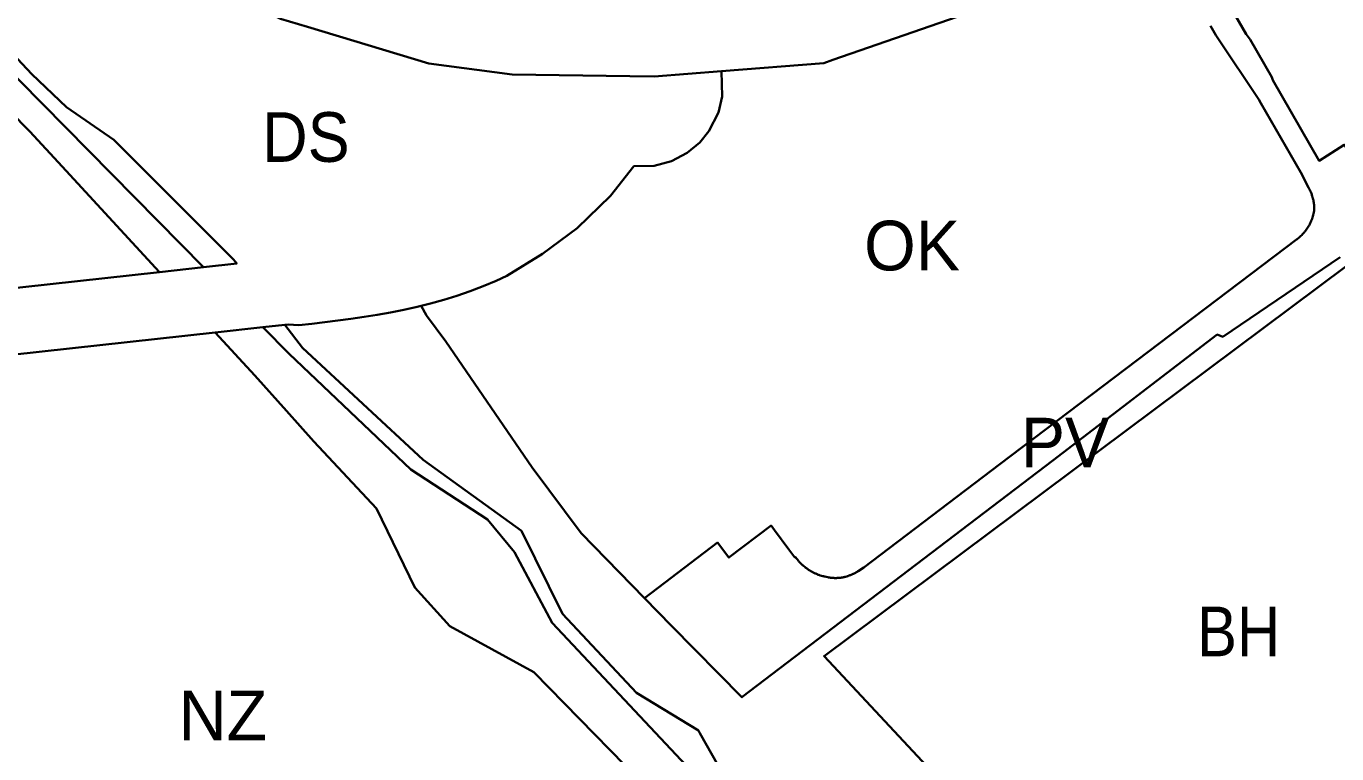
# Model space of a CAD drawing. Extents: x -650451 to -642268, y -1075216 to -1066610.
# Drawn here: x -646953.6 to -646557.7, y -1072322.1 to -1072102.4 of the extents above; entities that cross this region are included whole.
import ezdxf

# ---------------------------------------------------------------- set-up
doc = ezdxf.new("R2010")
doc.units = 0
doc.header["$LTSCALE"] = 6
doc.layers.add('1', color=7, linetype='Continuous', lineweight=35)
doc.layers.add('2', color=7, linetype='Continuous')
doc.layers.add('3', color=7, linetype='Continuous')

msp = doc.modelspace()

# ---------------------------------------------------------------- linework, layer by layer
at = {"layer": '1'}
for p, q in [((-646968.503, -1072182.672), (-646913.373, -1072176.618)), ((-646913.373, -1072176.618), (-646900.046, -1072175.154)), ((-646896.524, -1072194.888), (-646882.135, -1072193.308)), ((-646875.509, -1072192.58), (-646882.135, -1072193.308))]:
    msp.add_line(p, q, dxfattribs=at)
for points in [[(-647265.83, -1071793.64), (-647262.68, -1071796.7), (-647221.71, -1071838.15), (-647177.46, -1071886.9), (-647104.1, -1071962.84), (-647060.23, -1072007.95), (-647027.11, -1072042.92), (-646955.57, -1072118.88), (-646900.046, -1072175.154)], [(-646913.373, -1072176.618), (-646942.78, -1072144.74), (-646952.48, -1072134.22), (-646964.8, -1072121.83), (-646977.59, -1072108.96), (-646978.45, -1072108.09), (-647036.8, -1072048.41), (-647068.31, -1072015.68), (-647114.59, -1071967.77), (-647145.38, -1071935), (-647173.14, -1071905.45), (-647174.57, -1071904.06), (-647176.32, -1071902.3)], [(-646743.596, -1072115.986), (-646763.93, -1072117.61), (-646771.31, -1072117.49), (-646806.87, -1072116.94), (-646832.01, -1072113.66), (-646868.61, -1072102.6), (-646876.83, -1072100.12), (-646956.04, -1072061.95), (-646996.8, -1072034.35), (-647040.89, -1071996.58), (-647067.53, -1071967.54), (-647095.51, -1071938.39), (-647114.479, -1071912.479)], [(-646900.046, -1072175.154), (-646890.044, -1072174.056), (-646891.05, -1072172.79), (-646927.14, -1072136.74), (-646941.45, -1072126.84), (-646951.95, -1072116.84), (-646966.54, -1072101.4), (-646967.25, -1072100.6), (-646981.35, -1072085.77), (-647023.04, -1072041.63), (-647055.16, -1072007.74), (-647101.07, -1071960.24), (-647131.146, -1071929.146)], [(-646548.676, -1072166.737), (-646539.94, -1072160.83), (-646555.49, -1072138.17), (-646563.11, -1072143.03), (-646577.08, -1072118.7), (-646577.41, -1072117.76), (-646583.9, -1072106.42), (-646585.08, -1072104.81), (-646591.02, -1072094.4), (-646593.13, -1072091.01), (-646595.86, -1072086.82), (-646598.67, -1072081.55), (-646600.22, -1072077.86), (-646600.8, -1072075.94), (-646601.16, -1072074.07), (-646601.42, -1072071.01), (-646601, -1072067.55)], [(-646619.27, -1072080.81), (-646621.63, -1072079.85), (-646625.15, -1072078.98), (-646625.414, -1072079.188), (-646634.85, -1072086.5), (-646709.94, -1072112.55), (-646712.72, -1072113.52), (-646743.596, -1072115.986)], [(-646569.541, -1072166.508), (-646569.256, -1072166.279), (-646568.977, -1072166.042), (-646568.703, -1072165.797), (-646568.613, -1072165.714), (-646568.348, -1072165.458), (-646568.09, -1072165.196), (-646567.922, -1072165.017), (-646567.757, -1072164.835), (-646567.676, -1072164.743), (-646567.516, -1072164.556), (-646567.36, -1072164.367), (-646567.207, -1072164.175), (-646566.984, -1072163.882), (-646566.77, -1072163.583), (-646566.564, -1072163.279), (-646566.367, -1072162.971), (-646566.179, -1072162.657), (-646566.118, -1072162.552), (-646566, -1072162.34), (-646565.906, -1072162.16), (-646565.771, -1072161.887), (-646565.684, -1072161.703), (-646565.559, -1072161.424), (-646565.441, -1072161.142), (-646565.365, -1072160.952), (-646565.293, -1072160.761), (-646565.223, -1072160.569), (-646565.093, -1072160.181), (-646564.975, -1072159.789), (-646564.895, -1072159.493), (-646564.845, -1072159.295), (-646564.799, -1072159.096), (-646564.755, -1072158.896), (-646564.696, -1072158.596), (-646564.661, -1072158.395), (-646564.628, -1072158.194), (-646564.599, -1072157.993), (-646564.573, -1072157.792), (-646564.55, -1072157.59), (-646564.559, -1072157.196), (-646564.58, -1072156.802), (-646564.589, -1072156.671), (-646564.625, -1072156.276), (-646564.656, -1072156.013), (-646564.673, -1072155.882), (-646564.712, -1072155.62), (-646564.755, -1072155.358), (-646564.83, -1072154.967), (-646564.887, -1072154.707), (-646564.948, -1072154.449), (-646564.981, -1072154.32), (-646565.05, -1072154.064), (-646565.125, -1072153.808), (-646565.164, -1072153.681), (-646565.245, -1072153.429), (-646565.332, -1072153.178), (-646565.423, -1072152.929), (-646565.519, -1072152.683), (-646565.62, -1072152.438), (-646565.672, -1072152.317), (-646565.78, -1072152.076), (-646565.892, -1072151.838), (-646565.95, -1072151.72), (-646566.069, -1072151.486), (-646566.264, -1072151.112), (-646568.62, -1072146.55), (-646580.67, -1072125.63), (-646581.29, -1072124.56), (-646593.681, -1072106.013), (-646594.232, -1072105.088), (-646595.86, -1072102.267)], [(-646834.294, -1072186.789), (-646831.517, -1072186.103), (-646827.501, -1072184.997), (-646823.496, -1072183.769), (-646819.509, -1072182.408), (-646815.549, -1072180.906), (-646811.621, -1072179.254), (-646808.466, -1072177.78), (-646797.713, -1072171.151), (-646787.223, -1072163.402), (-646777.129, -1072153.576), (-646770.057, -1072144.677), (-646763.959, -1072144.535), (-646758.736, -1072143.137), (-646753.929, -1072140.612), (-646750.164, -1072137.467), (-646747.39, -1072134.069), (-646744.554, -1072128.415), (-646743.411, -1072123.612), (-646743.596, -1072115.986)], [(-646766.842, -1072275.063), (-646744.78, -1072258.29), (-646741.34, -1072262.83), (-646728.61, -1072253.17), (-646727.59, -1072254.59), (-646723.26, -1072260.35), (-646721.42, -1072262.78), (-646721.28, -1072262.7), (-646720.37, -1072263.85), (-646720.236, -1072263.999), (-646719.961, -1072264.294), (-646719.82, -1072264.439), (-646719.677, -1072264.582), (-646719.531, -1072264.723), (-646719.384, -1072264.863), (-646719.235, -1072265.001), (-646719.083, -1072265.138), (-646718.93, -1072265.272), (-646718.775, -1072265.405), (-646718.458, -1072265.664), (-646718.297, -1072265.79), (-646718.134, -1072265.915), (-646717.969, -1072266.038), (-646717.802, -1072266.158), (-646717.634, -1072266.276), (-646717.464, -1072266.392), (-646717.293, -1072266.506), (-646716.945, -1072266.727), (-646716.591, -1072266.938), (-646716.412, -1072267.04), (-646716.232, -1072267.14), (-646716.05, -1072267.237), (-646715.867, -1072267.332), (-646715.683, -1072267.424), (-646715.498, -1072267.514), (-646715.311, -1072267.601), (-646715.124, -1072267.685), (-646714.936, -1072267.767), (-646714.746, -1072267.847), (-646714.556, -1072267.924), (-646714.365, -1072267.998), (-646714.173, -1072268.069), (-646713.787, -1072268.205), (-646713.399, -1072268.329), (-646713.009, -1072268.443), (-646712.813, -1072268.496), (-646712.617, -1072268.546), (-646712.42, -1072268.594), (-646712.027, -1072268.681), (-646711.441, -1072268.8), (-646711.245, -1072268.835), (-646711.047, -1072268.867), (-646710.849, -1072268.896), (-646710.649, -1072268.922), (-646710.449, -1072268.944), (-646710.248, -1072268.963), (-646710.046, -1072268.979), (-646709.843, -1072268.992), (-646709.64, -1072269.001), (-646709.436, -1072269.007), (-646709.232, -1072269.009), (-646709.027, -1072269.008), (-646708.822, -1072269.004), (-646708.617, -1072268.996), (-646708.412, -1072268.985), (-646708.207, -1072268.97), (-646708.002, -1072268.952), (-646707.798, -1072268.93), (-646707.593, -1072268.905), (-646707.389, -1072268.877), (-646707.185, -1072268.844), (-646706.982, -1072268.809), (-646706.779, -1072268.77), (-646706.577, -1072268.728), (-646706.376, -1072268.682), (-646706.176, -1072268.633), (-646705.778, -1072268.525), (-646705.581, -1072268.465), (-646705.385, -1072268.403), (-646705.191, -1072268.338), (-646704.998, -1072268.269), (-646704.806, -1072268.197), (-646704.615, -1072268.122), (-646704.427, -1072268.044), (-646704.24, -1072267.963), (-646704.054, -1072267.879), (-646703.871, -1072267.792), (-646703.689, -1072267.703), (-646703.509, -1072267.61), (-646703.332, -1072267.515), (-646703.156, -1072267.417), (-646702.982, -1072267.317), (-646702.811, -1072267.214), (-646702.642, -1072267.108), (-646702.475, -1072267), (-646702.31, -1072266.89), (-646700.64, -1072265.79), (-646659.56, -1072234.65), (-646569.93, -1072166.8), (-646569.735, -1072166.656), (-646569.541, -1072166.508)], [(-646556.693, -1072172.159), (-646592.2, -1072196.17), (-646593.85, -1072195.48), (-646643.55, -1072233.5), (-646737.449, -1072305.019), (-646758.684, -1072283.41), (-646766.842, -1072275.063)], [(-646518.208, -1072321.92), (-646587.666, -1072389.082), (-646606.848, -1072405.785), (-646712.634, -1072292.59), (-646555.051, -1072174.933)], [(-646875.509, -1072192.58), (-646874.517, -1072192.471), (-646871.271, -1072192.675), (-646867.371, -1072192.234), (-646863.448, -1072191.771), (-646859.506, -1072191.276), (-646855.545, -1072190.741), (-646851.567, -1072190.155), (-646847.575, -1072189.507), (-646843.569, -1072188.789), (-646839.556, -1072187.988), (-646835.538, -1072187.097), (-646834.294, -1072186.789)], [(-646766.842, -1072275.063), (-646785.958, -1072255.505), (-646800.76, -1072235.668), (-646826.893, -1072197.582), (-646832.718, -1072189.697), (-646834.294, -1072186.789)], [(-646882.135, -1072193.308), (-646874.21, -1072201.34), (-646837.4, -1072236.27), (-646814.33, -1072251.34), (-646806.14, -1072261.22), (-646794.77, -1072282.59), (-646746.37, -1072333.94), (-646709.19, -1072376.06), (-646555.4, -1072536.38), (-646499.98, -1072594.11), (-646469.93, -1072603.28), (-646479.13, -1072616.26), (-646470.33, -1072617.33), (-646466.84, -1072620.18)], [(-646875.509, -1072192.58), (-646870.21, -1072199.51), (-646833.75, -1072233.32), (-646803.98, -1072254.74), (-646791.59, -1072279.78), (-646769.24, -1072303.65), (-646750.58, -1072315.02), (-646750.12, -1072315.82), (-646731.82, -1072348.2), (-646696.83, -1072385.81), (-646618.158, -1072468.098)], [(-646992.937, -1072205.475), (-646896.524, -1072194.888)], [(-646772.7, -1072325.66), (-646800.24, -1072297.4), (-646825.7, -1072283.54), (-646836.27, -1072271.9), (-646847.85, -1072247.99), (-646866.7, -1072227.81), (-646875, -1072218.53), (-646884.58, -1072207.83), (-646896.524, -1072194.888)]]:
    msp.add_lwpolyline(points, dxfattribs=at)

# ---------------------------------------------------------------- texts
at = {"layer": '2'}
for s, p in [('OK', (-646700.535, -1072176.126)), ('PV', (-646653.209, -1072235.631)), ('NZ', (-646907.559, -1072317.973))]:
    msp.add_text(s, height=15, dxfattribs=at).set_placement(p)
at = {"layer": '3'}
for s, width, p in [('DS', 0.95, (-646882.377, -1072143.348)), ('BH', 0.9, (-646599.94, -1072292.649))]:
    msp.add_text(s, height=15, dxfattribs=dict(at, width=width)).set_placement(p)

doc.saveas('drawing.dxf')
